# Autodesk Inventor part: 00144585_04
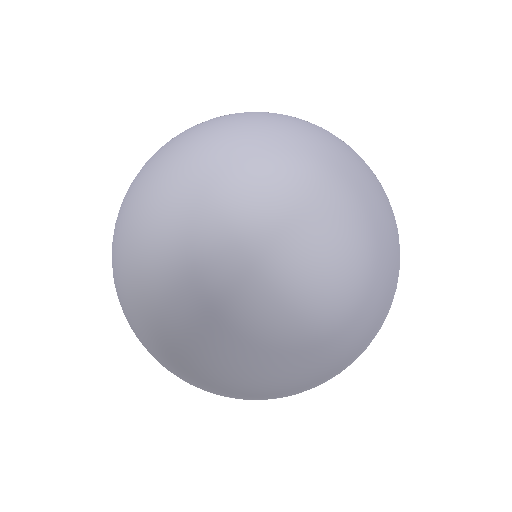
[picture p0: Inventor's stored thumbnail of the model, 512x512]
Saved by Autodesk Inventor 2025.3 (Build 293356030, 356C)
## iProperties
Created: 2021-02
Part Number: 00144585_04
Material: Generico
Document SubType Name: Modeling
Designer: R5800u
Density: 1 g/cm^3
Appearance: Default
Author: TraceParts
Sending System: SolidWorks 2021
Last Author: Albert
Last Saved: 2021-07-28
IsFastener: 1
TYPE: CATASM
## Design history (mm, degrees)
feature "Imported1"
node "Solido1"
